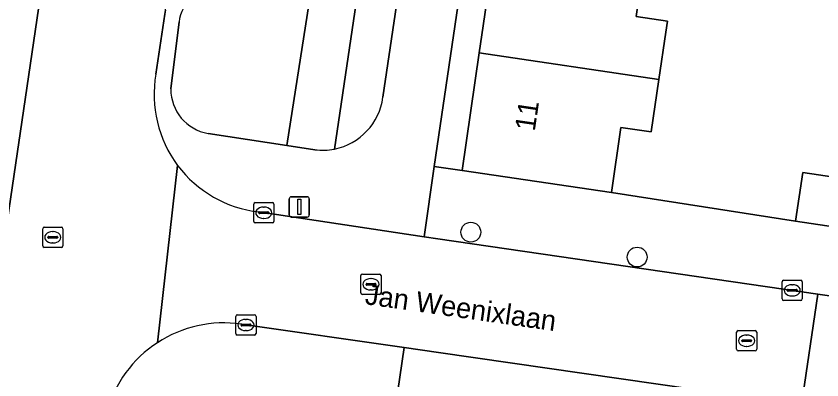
# Model space of a CAD drawing. Extents: x 163683 to 164494, y 382709 to 383872.
# Drawn here: x 163913.7 to 163953.58, y 383034.95 to 383052.94 of the extents above; entities that cross this region are included whole.
import ezdxf

# ---------------------------------------------------------------- set-up
doc = ezdxf.new("R2010")
doc.units = 0
for name, color, linetype in [('IMGEO_Boom', 7, 'Continuous'), ('IMGEO_Erf', 7, 'Continuous'), ('IMGEO_Groenvoorziening', 7, 'Continuous'), ('IMGEO_Kolk', 7, 'Continuous'), ('IMGEO_Lichtmast', 7, 'Continuous'), ('IMGEO_Muur', 7, 'Continuous'), ('IMGEO_Openbare_ruimte_label', 7, 'Continuous'), ('IMGEO_Pand', 7, 'Continuous'), ('IMGEO_Pand_nummerreeks', 7, 'Continuous'), ('IMGEO_Parkeervlak_open', 7, 'Continuous'), ('IMGEO_Rijbaan_lokaal_open', 7, 'Continuous'), ('IMGEO_Rioolput', 7, 'Continuous'), ('IMGEO_Voetpad_open', 7, 'Continuous')]:
    doc.layers.add(name, color=color, linetype=linetype)

msp = doc.modelspace()

# ---------------------------------------------------------------- linework, layer by layer
at = {"layer": 'IMGEO_Boom'}
for centre in [(163936.209, 383042.258), (163944.441, 383041.028)]:
    msp.add_circle(centre, 0.489, dxfattribs=at)
at = {"layer": 'IMGEO_Erf'}
msp.add_lwpolyline([(163941.068, 383081.248), (163939.693, 383081.384), (163934.389, 383045.511), (163935.774, 383045.317), (163936.629, 383051.121), (163937.52, 383057.167), (163938.381, 383063.014), (163939.261, 383068.983), (163940.129, 383074.874)], close=True, dxfattribs=at)
msp.add_lwpolyline([(163944.853, 383056.087), (163944.387, 383052.928), (163945.938, 383052.699), (163945.856, 383052.147), (163945.512, 383049.813), (163945.13, 383047.223), (163943.638, 383047.443), (163943.164, 383044.228), (163952.285, 383042.801), (163952.639, 383045.203), (163956.182, 383044.681)], dxfattribs=at)
at = {"layer": 'IMGEO_Groenvoorziening'}
for points in [[(163923.203, 383047.143), (163927.106, 383046.548), (163932.454, 383080.761), (163930.102, 383081.108)], [(163929.455, 383046.369), (163934.51, 383080.457), (163932.454, 383080.761), (163927.106, 383046.548), (163928.486, 383046.337)], [(163934.51, 383080.457), (163929.455, 383046.369)], [(163931.857, 383048.932), (163936.204, 383078.244)], [(163921.768, 383052.654), (163921.359, 383049.34)]]:
    msp.add_lwpolyline(points, dxfattribs=at)
for centre, radius, start, end in [((163923.483, 383052.48), 1.724, 126.4833, 174.2104), ((163923.576, 383049.329), 2.217, 179.7037, 260.3115), ((163928.873, 383049.322), 3.009, 281.1537, 352.5608), ((163928.872, 383049.342), 3.03, 262.6855, 281.0973)]:
    msp.add_arc(centre, radius, start, end, dxfattribs=at)
at = {"layer": 'IMGEO_Kolk'}
for p, q in [((163925.461, 383042.793), (163925.461, 383043.645)), ((163925.536, 383043.719), (163926.388, 383043.719)), ((163926.462, 383043.645), (163926.462, 383042.793)), ((163925.72, 383043.213), (163925.72, 383043.225)), ((163926.158, 383043.176), (163925.76, 383043.176)), ((163925.763, 383043.262), (163926.161, 383043.262)), ((163925.949, 383043.499), (163925.974, 383043.499)), ((163926.204, 383043.225), (163926.204, 383043.213)), ((163925.972, 383042.939), (163925.947, 383042.939)), ((163926.388, 383042.719), (163925.536, 383042.719)), ((163951.613, 383038.956), (163951.613, 383039.808)), ((163951.688, 383039.882), (163952.54, 383039.882)), ((163952.101, 383039.662), (163952.126, 383039.662)), ((163952.614, 383039.808), (163952.614, 383038.956)), ((163951.872, 383039.376), (163951.872, 383039.388)), ((163952.31, 383039.339), (163951.912, 383039.339)), ((163951.915, 383039.425), (163952.313, 383039.425)), ((163952.356, 383039.388), (163952.356, 383039.376)), ((163952.54, 383038.882), (163951.688, 383038.882)), ((163952.124, 383039.102), (163952.099, 383039.102)), ((163924.576, 383037.242), (163924.576, 383038.094)), ((163924.651, 383038.168), (163925.503, 383038.168)), ((163925.577, 383038.094), (163925.577, 383037.242)), ((163924.835, 383037.662), (163924.835, 383037.674)), ((163925.273, 383037.625), (163924.875, 383037.625)), ((163924.878, 383037.711), (163925.276, 383037.711)), ((163925.064, 383037.948), (163925.089, 383037.948)), ((163925.319, 383037.674), (163925.319, 383037.662)), ((163925.503, 383037.168), (163924.651, 383037.168)), ((163925.087, 383037.388), (163925.062, 383037.388))]:
    msp.add_line(p, q, dxfattribs=at)
for points in [[(163925.461, 383042.793), (163925.461, 383043.645)], [(163925.536, 383043.719), (163926.388, 383043.719)], [(163926.462, 383043.645), (163926.462, 383042.793)], [(163926.388, 383042.719), (163925.536, 383042.719)], [(163951.613, 383038.956), (163951.613, 383039.808)], [(163951.688, 383039.882), (163952.54, 383039.882)], [(163952.614, 383039.808), (163952.614, 383038.956)], [(163952.54, 383038.882), (163951.688, 383038.882)], [(163924.576, 383037.242), (163924.576, 383038.094)], [(163924.651, 383038.168), (163925.503, 383038.168)], [(163925.577, 383038.094), (163925.577, 383037.242)], [(163925.503, 383037.168), (163924.651, 383037.168)]]:
    msp.add_lwpolyline(points, dxfattribs=at)
for centre, radius, start, end in [((163925.538, 383043.643), 0.0765, 91.552, 178.448), ((163925.538, 383043.643), 0.0765, 91.552, 178.448), ((163926.386, 383043.643), 0.0765, 1.552, 88.448), ((163926.386, 383043.643), 0.0765, 1.552, 88.448), ((163925.76, 383043.222), 0.0403, 85.8775, 175.7526), ((163925.757, 383043.212), 0.0366, 178.938, 274.7102), ((163926.161, 383043.219), 0.043, 264.8664, 352.4533), ((163926.165, 383043.224), 0.0386, 1.7309, 96.639), ((163925.538, 383042.795), 0.0765, 181.552, 268.448), ((163925.538, 383042.795), 0.0765, 181.552, 268.448), ((163926.386, 383042.795), 0.0765, 271.552, 358.448), ((163926.386, 383042.795), 0.0765, 271.552, 358.448), ((163951.69, 383039.806), 0.0765, 91.552, 178.448), ((163951.69, 383039.806), 0.0765, 91.552, 178.448), ((163952.538, 383039.806), 0.0765, 1.552, 88.448), ((163952.538, 383039.806), 0.0765, 1.552, 88.448), ((163951.912, 383039.385), 0.0403, 85.8775, 175.7526), ((163951.909, 383039.375), 0.0366, 178.938, 274.7102), ((163952.313, 383039.382), 0.043, 264.8664, 352.4533), ((163952.317, 383039.387), 0.0386, 1.7309, 96.639), ((163951.69, 383038.958), 0.0765, 181.552, 268.448), ((163951.69, 383038.958), 0.0765, 181.552, 268.448), ((163952.538, 383038.958), 0.0765, 271.552, 358.448), ((163952.538, 383038.958), 0.0765, 271.552, 358.448), ((163924.653, 383038.092), 0.0765, 91.552, 178.448), ((163924.653, 383038.092), 0.0765, 91.552, 178.448), ((163925.501, 383038.092), 0.0765, 1.552, 88.448), ((163925.501, 383038.092), 0.0765, 1.552, 88.448), ((163924.875, 383037.671), 0.0403, 85.8775, 175.7526), ((163924.872, 383037.661), 0.0366, 178.938, 274.7102), ((163925.276, 383037.668), 0.043, 264.8664, 352.4533), ((163925.28, 383037.673), 0.0386, 1.7309, 96.639), ((163924.653, 383037.244), 0.0765, 181.552, 268.448), ((163924.653, 383037.244), 0.0765, 181.552, 268.448), ((163925.501, 383037.244), 0.0765, 271.552, 358.448), ((163925.501, 383037.244), 0.0765, 271.552, 358.448)]:
    msp.add_arc(centre, radius, start, end, dxfattribs=at)
for centre, major_axis, ratio, start_param, end_param in [((163925.948, 383043.219), (-0.387, 0.002), 0.722429, 4.712389, 7.853982), ((163925.973, 383043.219), (-0.39, 0.002), 0.717154, 1.570796, 4.712389), ((163952.1, 383039.382), (-0.387, 0.002), 0.722429, 4.712389, 7.853982), ((163952.125, 383039.382), (-0.39, 0.002), 0.717154, 1.570796, 4.712389), ((163925.063, 383037.668), (-0.387, 0.002), 0.722429, 4.712389, 7.853982), ((163925.088, 383037.668), (-0.39, 0.002), 0.717154, 1.570796, 4.712389)]:
    msp.add_ellipse(centre, major_axis=major_axis, ratio=ratio, start_param=start_param, end_param=end_param, dxfattribs=at)
at = {"layer": 'IMGEO_Lichtmast'}
for p, q in [((163927.321, 383044.009), (163928.111, 383044.009)), ((163928.111, 383044.009), (163927.321, 383044.009)), ((163927.221, 383043.109), (163927.221, 383043.909)), ((163927.221, 383043.909), (163927.221, 383043.109)), ((163928.211, 383043.909), (163928.211, 383043.109)), ((163928.211, 383043.109), (163928.211, 383043.909)), ((163928.111, 383043.009), (163927.321, 383043.009)), ((163927.321, 383043.009), (163928.111, 383043.009))]:
    msp.add_line(p, q, dxfattribs=at)
msp.add_lwpolyline([(163927.641, 383043.884), (163927.791, 383043.884), (163927.791, 383043.134), (163927.641, 383043.134), (163927.641, 383043.884)], dxfattribs=at)
for centre, start, end in [((163927.321, 383043.909), 90, 180), ((163927.321, 383043.909), 90, 180), ((163928.111, 383043.909), 0, 90), ((163928.111, 383043.909), 360, 90), ((163927.321, 383043.109), 180, 270), ((163927.321, 383043.109), 180, 270), ((163928.111, 383043.109), 270, 0), ((163928.111, 383043.109), 270, 0)]:
    msp.add_arc(centre, 0.1, start, end, dxfattribs=at)
at = {"layer": 'IMGEO_Muur'}
msp.add_lwpolyline([(163943.164, 383044.228), (163952.285, 383042.801)], dxfattribs=at)
at = {"layer": 'IMGEO_Pand'}
for points in [[(163945.512, 383049.813), (163945.856, 383052.147), (163945.938, 383052.699), (163944.387, 383052.928), (163944.853, 383056.087), (163937.52, 383057.167), (163936.629, 383051.121)], [(163945.512, 383049.813), (163936.629, 383051.121), (163935.774, 383045.317), (163943.164, 383044.228), (163943.638, 383047.443), (163945.13, 383047.223)], [(163952.285, 383042.801), (163955.828, 383042.279), (163956.182, 383044.681), (163952.639, 383045.203)]]:
    msp.add_lwpolyline(points, close=True, dxfattribs=at)
at = {"layer": 'IMGEO_Parkeervlak_open'}
msp.add_lwpolyline([(163906.683, 382998.169), (163915.86, 383060.494)], dxfattribs=at)
at = {"layer": 'IMGEO_Rijbaan_lokaal_open'}
for points in [[(163927.073, 383093.609), (163927.986, 383100.088), (163928.07, 383100.498), (163930.242, 383115.507), (163930.286, 383115.815), (163930.41, 383116.649), (163924.273, 383117.548), (163923.937, 383115.2), (163923.888, 383114.947), (163916.287, 383063.139), (163915.969, 383060.927), (163915.86, 383060.494), (163906.683, 382998.169), (163904.947, 382986.544), (163904.878, 382985.967)], [(163920.621, 383050.069), (163921.064, 383053.038), (163921.093, 383053.234), (163925.454, 383081.51)], [(163920.698, 383036.793), (163921.699, 383045.563)], [(163921.699, 383045.563), (163920.698, 383036.793)], [(163953.381, 383039.199), (163934.575, 383041.928), (163933.891, 383042.031), (163925.719, 383043.258)], [(163924.842, 383037.712), (163932.906, 383036.552), (163934.614, 383036.306), (163952.581, 383033.717), (163953.381, 383039.199)]]:
    msp.add_lwpolyline(points, dxfattribs=at)
msp.add_lwpolyline([(163956.003, 383038.814), (163953.381, 383039.199), (163952.581, 383033.717), (163955.204, 383033.334)], close=True, dxfattribs=at)
for centre, radius, start, end in [((163926.375, 383049.064), 5.841, 170.0877, 216.821), ((163926.378, 383049.066), 5.845, 216.8175, 263.524), ((163923.993, 383031.738), 6.034, 81.912, 123.0958), ((163923.996, 383031.736), 6.037, 123.1133, 164.2701)]:
    msp.add_arc(centre, radius, start, end, dxfattribs=at)
at = {"layer": 'IMGEO_Rioolput'}
for p, q in [((163915.018, 383041.579), (163915.018, 383042.431)), ((163915.093, 383042.505), (163915.945, 383042.505)), ((163916.019, 383042.431), (163916.019, 383041.579)), ((163915.277, 383041.999), (163915.277, 383042.011)), ((163915.715, 383041.962), (163915.317, 383041.962)), ((163915.32, 383042.048), (163915.718, 383042.048)), ((163915.506, 383042.285), (163915.531, 383042.285)), ((163915.761, 383042.011), (163915.761, 383041.999)), ((163915.529, 383041.725), (163915.504, 383041.725)), ((163915.945, 383041.505), (163915.093, 383041.505)), ((163930.765, 383039.257), (163930.765, 383040.109)), ((163930.84, 383040.183), (163931.692, 383040.183)), ((163931.253, 383039.963), (163931.278, 383039.963)), ((163931.766, 383040.109), (163931.766, 383039.257)), ((163931.024, 383039.677), (163931.024, 383039.689)), ((163931.462, 383039.64), (163931.064, 383039.64)), ((163931.067, 383039.726), (163931.465, 383039.726)), ((163931.508, 383039.689), (163931.508, 383039.677)), ((163931.692, 383039.183), (163930.84, 383039.183)), ((163931.276, 383039.403), (163931.251, 383039.403)), ((163949.359, 383036.465), (163949.359, 383037.317)), ((163949.434, 383037.391), (163950.286, 383037.391)), ((163949.847, 383037.171), (163949.872, 383037.171)), ((163950.36, 383037.317), (163950.36, 383036.465)), ((163949.618, 383036.885), (163949.618, 383036.897)), ((163950.056, 383036.848), (163949.658, 383036.848)), ((163949.661, 383036.934), (163950.059, 383036.934)), ((163950.102, 383036.897), (163950.102, 383036.885)), ((163950.286, 383036.391), (163949.434, 383036.391)), ((163949.87, 383036.611), (163949.845, 383036.611))]:
    msp.add_line(p, q, dxfattribs=at)
for points in [[(163915.018, 383041.579), (163915.018, 383042.431)], [(163915.093, 383042.505), (163915.945, 383042.505)], [(163916.019, 383042.431), (163916.019, 383041.579)], [(163915.945, 383041.505), (163915.093, 383041.505)], [(163930.765, 383039.257), (163930.765, 383040.109)], [(163930.84, 383040.183), (163931.692, 383040.183)], [(163931.766, 383040.109), (163931.766, 383039.257)], [(163931.692, 383039.183), (163930.84, 383039.183)], [(163949.359, 383036.465), (163949.359, 383037.317)], [(163949.434, 383037.391), (163950.286, 383037.391)], [(163950.36, 383037.317), (163950.36, 383036.465)], [(163950.286, 383036.391), (163949.434, 383036.391)]]:
    msp.add_lwpolyline(points, dxfattribs=at)
for centre, radius, start, end in [((163915.095, 383042.429), 0.0765, 91.552, 178.448), ((163915.095, 383042.429), 0.0765, 91.552, 178.448), ((163915.943, 383042.429), 0.0765, 1.552, 88.448), ((163915.943, 383042.429), 0.0765, 1.552, 88.448), ((163915.317, 383042.008), 0.0403, 85.8775, 175.7526), ((163915.314, 383041.998), 0.0366, 178.938, 274.7102), ((163915.718, 383042.005), 0.043, 264.8664, 352.4533), ((163915.722, 383042.01), 0.0386, 1.7309, 96.639), ((163915.095, 383041.581), 0.0765, 181.552, 268.448), ((163915.095, 383041.581), 0.0765, 181.552, 268.448), ((163915.943, 383041.581), 0.0765, 271.552, 358.448), ((163915.943, 383041.581), 0.0765, 271.552, 358.448), ((163930.842, 383040.107), 0.0765, 91.552, 178.448), ((163930.842, 383040.107), 0.0765, 91.552, 178.448), ((163931.69, 383040.107), 0.0765, 1.552, 88.448), ((163931.69, 383040.107), 0.0765, 1.552, 88.448), ((163931.064, 383039.686), 0.0403, 85.8775, 175.7526), ((163931.061, 383039.676), 0.0366, 178.938, 274.7102), ((163931.465, 383039.683), 0.043, 264.8664, 352.4533), ((163931.469, 383039.688), 0.0386, 1.7309, 96.639), ((163930.842, 383039.259), 0.0765, 181.552, 268.448), ((163930.842, 383039.259), 0.0765, 181.552, 268.448), ((163931.69, 383039.259), 0.0765, 271.552, 358.448), ((163931.69, 383039.259), 0.0765, 271.552, 358.448), ((163949.436, 383037.315), 0.0765, 91.552, 178.448), ((163949.436, 383037.315), 0.0765, 91.552, 178.448), ((163950.284, 383037.315), 0.0765, 1.552, 88.448), ((163950.284, 383037.315), 0.0765, 1.552, 88.448), ((163949.658, 383036.894), 0.0403, 85.8775, 175.7526), ((163949.655, 383036.884), 0.0366, 178.938, 274.7102), ((163950.059, 383036.891), 0.043, 264.8664, 352.4533), ((163950.063, 383036.896), 0.0386, 1.7309, 96.639), ((163949.436, 383036.467), 0.0765, 181.552, 268.448), ((163949.436, 383036.467), 0.0765, 181.552, 268.448), ((163950.284, 383036.467), 0.0765, 271.552, 358.448), ((163950.284, 383036.467), 0.0765, 271.552, 358.448)]:
    msp.add_arc(centre, radius, start, end, dxfattribs=at)
for centre, major_axis, ratio, start_param, end_param in [((163915.505, 383042.005), (-0.387, 0.002), 0.722429, 4.712389, 7.853982), ((163915.53, 383042.005), (-0.39, 0.002), 0.717154, 1.570796, 4.712389), ((163931.252, 383039.683), (-0.387, 0.002), 0.722429, 4.712389, 7.853982), ((163931.277, 383039.683), (-0.39, 0.002), 0.717154, 1.570796, 4.712389), ((163949.846, 383036.891), (-0.387, 0.002), 0.722429, 4.712389, 7.853982), ((163949.871, 383036.891), (-0.39, 0.002), 0.717154, 1.570796, 4.712389)]:
    msp.add_ellipse(centre, major_axis=major_axis, ratio=ratio, start_param=start_param, end_param=end_param, dxfattribs=at)
at = {"layer": 'IMGEO_Voetpad_open'}
for points in [[(163925.719, 383043.258), (163933.891, 383042.031), (163934.389, 383045.511), (163939.693, 383081.384), (163940.003, 383083.479)], [(163936.204, 383078.244), (163931.857, 383048.932)], [(163921.093, 383053.234), (163921.064, 383053.038), (163920.621, 383050.069)], [(163921.359, 383049.34), (163921.768, 383052.654)], [(163928.486, 383046.337), (163927.106, 383046.548), (163923.203, 383047.143)], [(163961.128, 383041.5), (163957.633, 383042.015), (163955.828, 383042.279), (163952.285, 383042.801), (163943.164, 383044.228), (163935.774, 383045.317), (163934.389, 383045.511), (163933.891, 383042.031), (163934.575, 383041.928), (163953.381, 383039.199), (163956.003, 383038.814), (163976.752, 383035.761)], [(163926.828, 382994.736), (163928.008, 382994.649), (163928.427, 382997.43), (163927.27, 382997.607), (163932.479, 383033.616), (163932.906, 383036.552), (163924.842, 383037.712)]]:
    msp.add_lwpolyline(points, dxfattribs=at)
msp.add_lwpolyline([(163952.581, 383033.717), (163934.614, 383036.306), (163932.906, 383036.552), (163932.479, 383033.616), (163933.722, 383033.434), (163942.533, 383032.141), (163946.156, 383031.609), (163950.603, 383030.987), (163954.126, 383030.47), (163955.879, 383030.205), (163956.386, 383030.131), (163956.493, 383033.146), (163955.204, 383033.334)], close=True, dxfattribs=at)
for centre, radius, start, end in [((163923.483, 383052.48), 1.724, 126.4833, 174.2104), ((163926.375, 383049.064), 5.841, 170.0877, 216.821), ((163923.576, 383049.329), 2.217, 179.7037, 260.3115), ((163928.873, 383049.322), 3.009, 281.1537, 352.5608), ((163928.872, 383049.342), 3.03, 262.6855, 281.0973), ((163926.378, 383049.066), 5.845, 216.8175, 263.524), ((163923.993, 383031.738), 6.034, 81.912, 123.0958), ((163923.996, 383031.736), 6.037, 123.1133, 164.2701)]:
    msp.add_arc(centre, radius, start, end, dxfattribs=at)

# ---------------------------------------------------------------- texts
at = {"layer": 'IMGEO_Openbare_ruimte_label'}
msp.add_text('Jan Weenixlaan', height=1, rotation=351.8942, dxfattribs=at).set_placement((163930.936, 383038.704))
at = {"layer": 'IMGEO_Pand_nummerreeks'}
msp.add_text('11', height=1, rotation=81.6185, dxfattribs=at).set_placement((163939.37, 383047.219))

doc.saveas('drawing.dxf')
